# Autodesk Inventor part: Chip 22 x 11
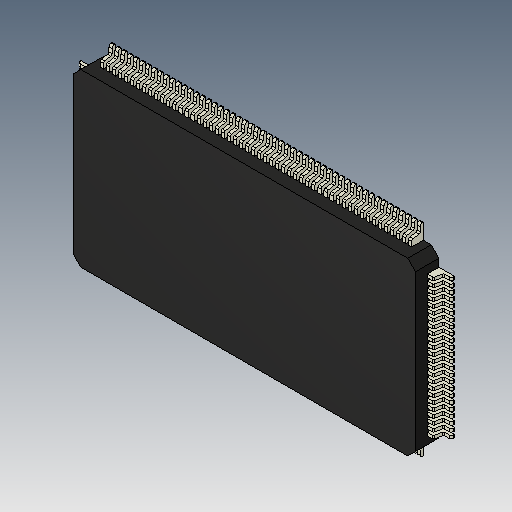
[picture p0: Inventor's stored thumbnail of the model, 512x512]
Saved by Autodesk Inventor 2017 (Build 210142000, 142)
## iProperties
Created: 2005-12
Part Number: Chip 22 x 11
Material: Generic
Document SubType Name: Modeling
Designer: DanielSeverino
Density: 1 g/cm^3
Appearance: Default
Author: DanielSeverino
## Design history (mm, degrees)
feature "Solid1"
body "Solid2"
